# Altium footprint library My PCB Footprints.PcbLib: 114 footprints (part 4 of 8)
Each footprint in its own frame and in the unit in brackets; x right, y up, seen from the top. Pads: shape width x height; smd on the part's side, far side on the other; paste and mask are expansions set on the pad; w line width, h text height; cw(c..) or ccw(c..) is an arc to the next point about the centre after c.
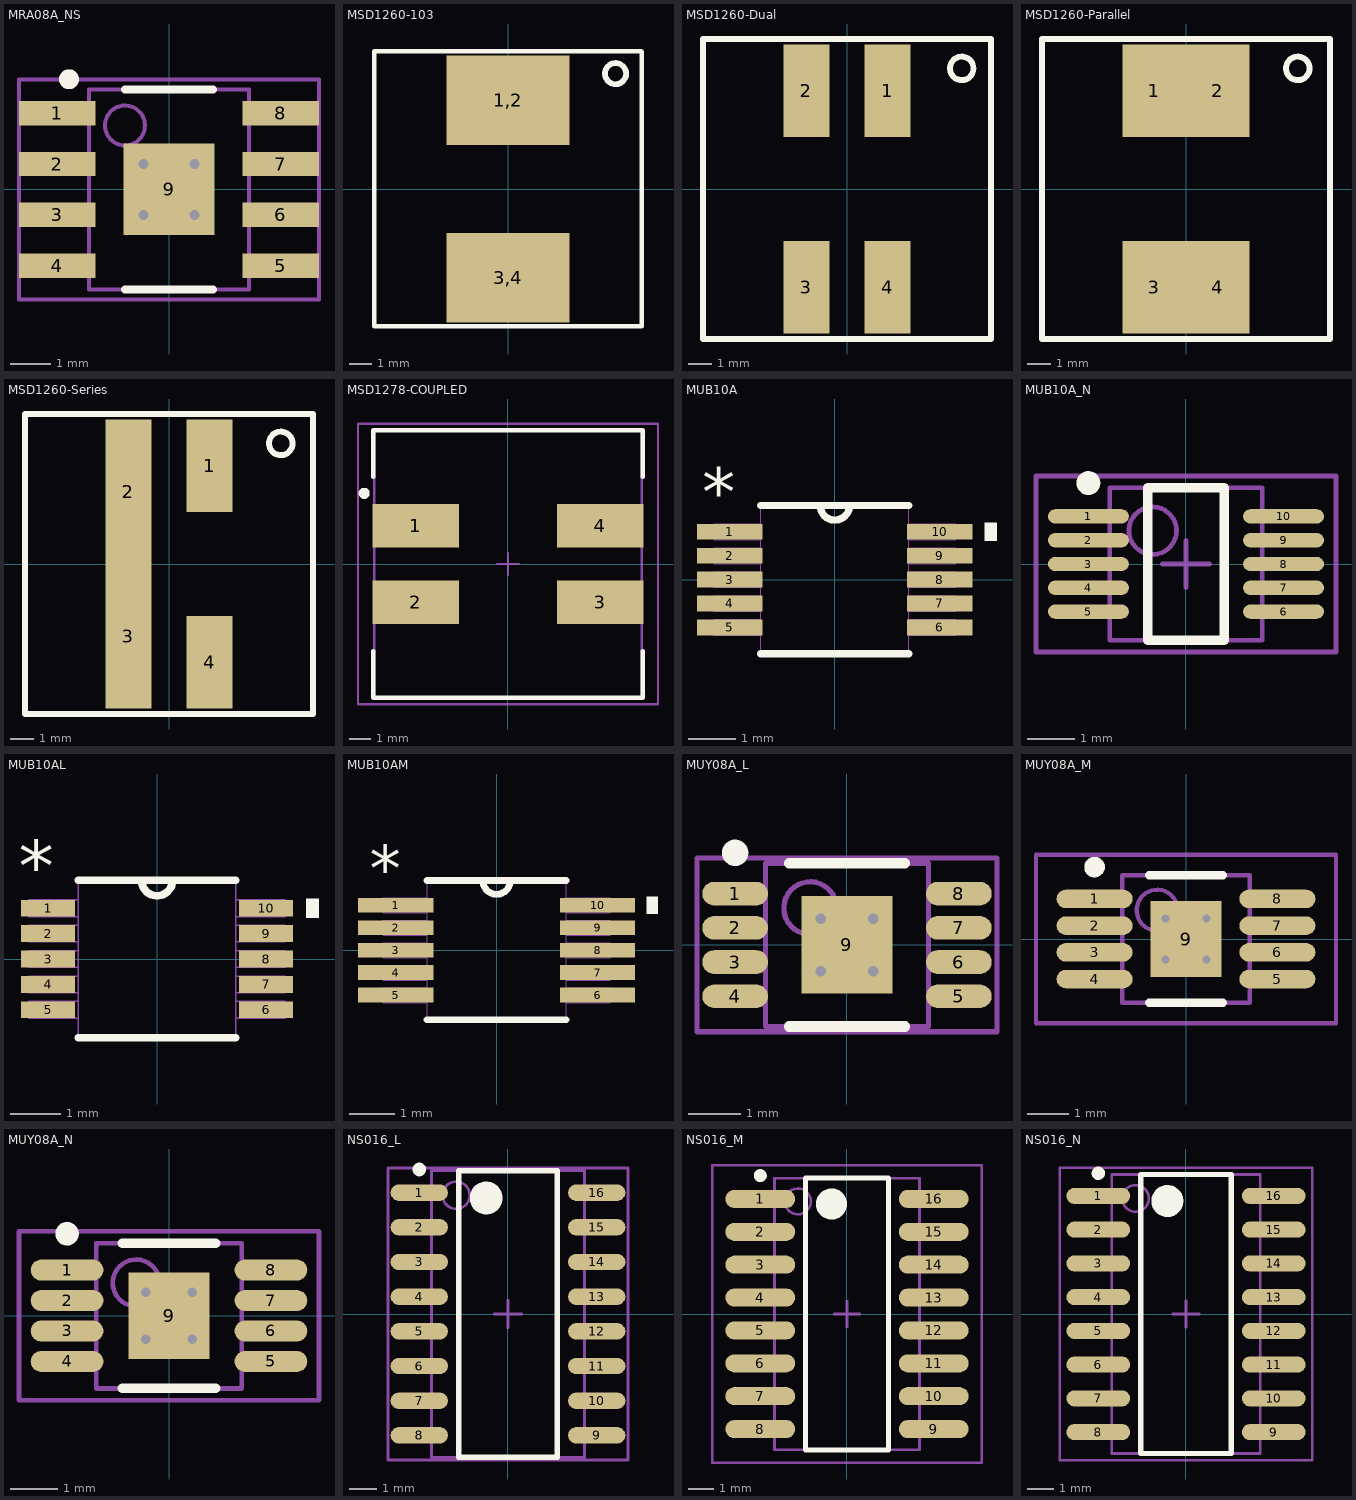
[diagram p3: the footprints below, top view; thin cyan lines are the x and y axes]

## MRA08A_NS [mil] "SOIC, 8-Leads, Body 193x154mil, Pitch 50mil, Exposed Pad, NS Recommended Footprint"
height 66
pads (9):
  rect 75x24 smd: 1(-110,75) 2(-110,25) 3(-110,-25) 4(-110,-75) 5(110,-75) 6(110,-25) 7(110,25) 8(110,75)
  rect 90x90 smd: 9(0,0)
via -25,-25 diameter 25 hole 10
via 25,-25 diameter 25 hole 10
via 25,25 diameter 25 hole 10
via -25,25 diameter 25 hole 10
Top Overlay:
  circle w9.84: c-98.43,108.46 r4.92
  lines w7.87: -43.31,-98.43 43.31,-98.43 ; -43.31,98.43 43.31,98.43
Mechanical 5:
  text ".Designator" at -60,-20 h40
Mechanical 13:
  circle w3.94: c-43.31,62.99 r19.68
  lines w3.94: -78.74,-98.43 78.74,-98.43 78.74,98.43 -78.74,98.43 -78.74,-98.43
Mechanical 15:
  lines w3.94: -19.68,0 19.68,0 ; 0,-19.68 0,19.68 ; -147.64,-108.27 147.64,-108.27 147.64,108.27 -147.64,108.27 -147.64,-108.27
3D body: height 66.14, standoff 0.98, extent -78.74,-98.43 78.74,98.43

## MSD1260-103 [mm]
pads (2):
  rect 5.5x4 smd: 1,2(0,3.978) 3,4(0,-3.978)
Top Overlay:
  circle w0.254: c4.825,5.175 r0.475
  lines w0.2: 6,-6.15 -6,-6.15 -6,6.175 5.975,6.175 6,6.15 6,-6.1

## MSD1260-Dual [mm]
height 6
pads (4):
  rect 2x4 smd: 1(1.75,4.25) 2(-1.75,4.25) 3(-1.75,-4.25) 4(1.75,-4.25)
Top Overlay:
  circle w0.254: c4.953,5.207 r0.508
  lines w0.254: -6.223,-6.477 -6.223,6.477 6.223,6.477 6.223,-6.477 -6.223,-6.477

## MSD1260-Parallel [mm]
height 6
pads (4):
  rect 2.75x4 smd: 1(-1.375,4.25) 2(1.375,4.25) 3(-1.375,-4.25) 4(1.375,-4.25)
Top Overlay:
  circle w0.254: c4.826,5.207 r0.508
  lines w0.254: -6.223,-6.477 6.223,-6.477 6.223,6.477 -6.223,6.477 -6.223,-6.477

## MSD1260-Series [mm]
height 6
pads (4):
  rect 2x4 smd: 1(1.75,4.25) 4(1.75,-4.25)
  rect 2x6.25 smd: 2(-1.75,3.125) 3(-1.75,-3.125)
Top Overlay:
  circle w0.254: c4.826,5.207 r0.508
  lines w0.254: -6.223,-6.477 6.223,-6.477 6.223,6.477 -6.223,6.477 -6.223,-6.477

## MSD1278-COUPLED [mil]
height 316.93
pads (4):
  rect 157x79 smd mask+2: 1(-167.32,69) 2(-167.32,-69) 3(167.32,-69) 4(167.32,69)
Top Overlay:
  circle w10: c-260.41,128.06 r5.03
  lines w7.87: -244.09,-157.48 -244.09,-242.13 244.09,-242.13 244.09,-157.48 ; -244.09,157.48 -244.09,242.13 244.09,242.13 244.09,157.48
Mechanical 5:
  text ".Designator" at -60,-20 h40
Mechanical 13:
  lines w3.94: -242.13,-242.13 -242.13,242.13 242.13,242.13 242.13,-242.13 -242.13,-242.13
Mechanical 15:
  lines w3.94: -19.68,0 19.69,0 ; 0,-19.68 0,19.69 ; -271.65,-253.94 -271.65,253.94 271.65,253.94 271.65,-253.94 -271.65,-253.94
3D body: height 316.93, standoff 0, extent -242.13,-242.13 242.13,242.13

## MUB10A [mil]
pads (10):
  rect 54x13 smd: 1(-86.5,39.37) 2(-86.5,19.68) 3(-86.5,0) 4(-86.5,-19.68) 5(-86.5,-39.37) 6(86.5,-39.37) 7(86.5,-19.68) 8(86.5,0) 9(86.5,19.68) 10(86.5,39.37)
Top Overlay:
  region: 133.5,46.87 133.5,31.87 123.5,31.87 123.5,46.87
  lines w6: -61,-61 61,-61 ; -61,61 61,61 ; -12,61 ccw(c0,61) 12,61
  text "*" at -109.02,52.02 h40
Mechanical 1:
  lines w1: -12,61 ccw(c0,61) 12,61 ; -99.5,-45.87 -99.5,-32.87 -61,-32.87 -61,-45.87 -99.5,-45.87 ; -99.5,-26.18 -99.5,-13.19 -61,-13.19 -61,-26.18 -99.5,-26.18 ; -99.5,-6.5 -99.5,6.5 -61,6.5 -61,-6.5 -99.5,-6.5 ; -99.5,13.19 -99.5,26.18 -61,26.18 -61,13.19 -99.5,13.19 ; -99.5,32.87 -99.5,45.87 -61,45.87 -61,32.87 -99.5,32.87 ; -61,-61 61,-61 61,61 -61,61 -61,-61 ; 61,-45.87 61,-32.87 99.5,-32.87 99.5,-45.87 61,-45.87 ; 61,-26.18 61,-13.19 99.5,-13.19 99.5,-26.18 61,-26.18 ; 61,-6.5 61,6.5 99.5,6.5 99.5,-6.5 61,-6.5 ; 61,13.19 61,26.18 99.5,26.18 99.5,13.19 61,13.19 ; 61,32.87 61,45.87 99.5,45.87 99.5,32.87 61,32.87
  text "*" at -109.02,52.02 h40

## MUB10A_N [mm] "TSSOP, 10-Leads, Body 3x3mm, Pitch 0.5mm, IPC Medium Density"
height 1.09
pads (10):
  oval 1.7x0.3 smd: 1(-2.05,1) 2(-2.05,0.5) 3(-2.05,0) 4(-2.05,-0.5) 5(-2.05,-1) 6(2.05,-1) 7(2.05,-0.5) 8(2.05,0) 9(2.05,0.5) 10(2.05,1)
Top Overlay:
  circle w0.25: c-2.05,1.7 r0.125
  lines w0.2: -0.8,-1.6 -0.8,1.6 0.8,1.6 0.8,-1.6 -0.8,-1.6
Mechanical 5:
  circle w0.1: c-0.7,0.7 r0.5
  lines w0.1: -1.6,-1.6 -1.6,1.6 1.6,1.6 1.6,-1.6 -1.6,-1.6
  text ".Designator" at -1.524,-0.508 h1.02
Mechanical 15:
  lines w0.1: -0.5,0 0.5,0 ; 0,-0.5 0,0.5 ; -3.15,-1.85 -3.15,1.85 3.15,1.85 3.15,-1.85 -3.15,-1.85
3D body: height 1.09, standoff 0, extent -1.6,-1.6 1.6,1.6

## MUB10AL [mil]
pads (10):
  rect 42x13 smd: 1(-84.5,39.37) 2(-84.5,19.68) 3(-84.5,0) 4(-84.5,-19.68) 5(-84.5,-39.37) 6(84.5,-39.37) 7(84.5,-19.68) 8(84.5,0) 9(84.5,19.68) 10(84.5,39.37)
Top Overlay:
  region: 125.5,46.87 125.5,31.87 115.5,31.87 115.5,46.87
  lines w6: -61,-61 61,-61 ; -61,61 61,61 ; -12,61 ccw(c0,61) 12,61
  text "*" at -107.02,52.02 h40
Mechanical 1:
  lines w1: -12,61 ccw(c0,61) 12,61 ; -99.5,-45.87 -99.5,-32.87 -61,-32.87 -61,-45.87 -99.5,-45.87 ; -99.5,-26.18 -99.5,-13.19 -61,-13.19 -61,-26.18 -99.5,-26.18 ; -99.5,-6.5 -99.5,6.5 -61,6.5 -61,-6.5 -99.5,-6.5 ; -99.5,13.19 -99.5,26.18 -61,26.18 -61,13.19 -99.5,13.19 ; -99.5,32.87 -99.5,45.87 -61,45.87 -61,32.87 -99.5,32.87 ; -61,-61 61,-61 61,61 -61,61 -61,-61 ; 61,-45.87 61,-32.87 99.5,-32.87 99.5,-45.87 61,-45.87 ; 61,-26.18 61,-13.19 99.5,-13.19 99.5,-26.18 61,-26.18 ; 61,-6.5 61,6.5 99.5,6.5 99.5,-6.5 61,-6.5 ; 61,13.19 61,26.18 99.5,26.18 99.5,13.19 61,13.19 ; 61,32.87 61,45.87 99.5,45.87 99.5,32.87 61,32.87
  text "*" at -107.02,52.02 h40

## MUB10AM [mil]
pads (10):
  rect 66x13 smd: 1(-88.5,39.37) 2(-88.5,19.68) 3(-88.5,0) 4(-88.5,-19.68) 5(-88.5,-39.37) 6(88.5,-39.37) 7(88.5,-19.68) 8(88.5,0) 9(88.5,19.68) 10(88.5,39.37)
Top Overlay:
  region: 141.5,46.87 141.5,31.87 131.5,31.87 131.5,46.87
  lines w6: -61,-61 61,-61 ; -61,61 61,61 ; -12,61 ccw(c0,61) 12,61
  text "*" at -111.02,52.02 h40
Mechanical 1:
  lines w1: -12,61 ccw(c0,61) 12,61 ; -99.5,-45.87 -99.5,-32.87 -61,-32.87 -61,-45.87 -99.5,-45.87 ; -99.5,-26.18 -99.5,-13.19 -61,-13.19 -61,-26.18 -99.5,-26.18 ; -99.5,-6.5 -99.5,6.5 -61,6.5 -61,-6.5 -99.5,-6.5 ; -99.5,13.19 -99.5,26.18 -61,26.18 -61,13.19 -99.5,13.19 ; -99.5,32.87 -99.5,45.87 -61,45.87 -61,32.87 -99.5,32.87 ; -61,-61 61,-61 61,61 -61,61 -61,-61 ; 61,-45.87 61,-32.87 99.5,-32.87 99.5,-45.87 61,-45.87 ; 61,-26.18 61,-13.19 99.5,-13.19 99.5,-26.18 61,-26.18 ; 61,-6.5 61,6.5 99.5,6.5 99.5,-6.5 61,-6.5 ; 61,13.19 61,26.18 99.5,26.18 99.5,13.19 61,13.19 ; 61,32.87 61,45.87 99.5,45.87 99.5,32.87 61,32.87
  text "*" at -111.02,52.02 h40

## MUY08A_L [mm] "TSOP, 8-Leads, Body 3x3mm, Pitch 0.65mm, Exposed Pad, IPC High Density"
height 1.09
pads (9):
  oval 1.25x0.45 smd: 1(-2.125,0.975) 2(-2.125,0.325) 3(-2.125,-0.325) 4(-2.125,-0.975) 5(2.125,-0.975) 6(2.125,-0.325) 7(2.125,0.325) 8(2.125,0.975)
  rect 1.73x1.85 smd: 9(0,0)
via 0.5,-0.5 diameter 0.4 hole 0.2
via -0.5,-0.5 diameter 0.4 hole 0.2
via 0.5,0.5 diameter 0.4 hole 0.2
via -0.5,0.5 diameter 0.4 hole 0.2
Top Overlay:
  circle w0.25: c-2.125,1.75 r0.125
  lines w0.2: -1.1,-1.55 1.1,-1.55 ; -1.1,1.55 1.1,1.55
Mechanical 5:
  text ".Designator" at -1.524,-0.508 h1.02
Mechanical 13:
  circle w0.1: c-0.7,0.7 r0.5
  lines w0.1: -1.55,-1.55 1.55,-1.55 1.55,1.55 -1.55,1.55 -1.55,-1.55
Mechanical 15:
  lines w0.1: -0.5,0 0.5,0 ; 0,-0.5 0,0.5 ; -2.85,-1.65 2.85,-1.65 2.85,1.65 -2.85,1.65 -2.85,-1.65
3D body: height 1.09, standoff 0, extent -1.549,-1.549 1.549,1.549

## MUY08A_M [mm] "TSOP, 8-Leads, Body 3x3mm, Pitch 0.65mm, Exposed Pad, IPC Low Density"
height 1.09
pads (9):
  oval 1.85x0.45 smd: 1(-2.225,0.975) 2(-2.225,0.325) 3(-2.225,-0.325) 4(-2.225,-0.975) 5(2.225,-0.975) 6(2.225,-0.325) 7(2.225,0.325) 8(2.225,0.975)
  rect 1.73x1.85 smd: 9(0,0)
via 0.5,-0.5 diameter 0.4 hole 0.2
via -0.5,-0.5 diameter 0.4 hole 0.2
via 0.5,0.5 diameter 0.4 hole 0.2
via -0.5,0.5 diameter 0.4 hole 0.2
Top Overlay:
  circle w0.25: c-2.225,1.75 r0.125
  lines w0.2: -0.9,-1.55 0.9,-1.55 ; -0.9,1.55 0.9,1.55
Mechanical 5:
  text ".Designator" at -1.524,-0.508 h1.02
Mechanical 13:
  circle w0.1: c-0.7,0.7 r0.5
  lines w0.1: -1.55,-1.55 1.55,-1.55 1.55,1.55 -1.55,1.55 -1.55,-1.55
Mechanical 15:
  lines w0.1: -0.5,0 0.5,0 ; 0,-0.5 0,0.5 ; -3.65,-2.05 3.65,-2.05 3.65,2.05 -3.65,2.05 -3.65,-2.05
3D body: height 1.09, standoff 0, extent -1.549,-1.549 1.549,1.549

## MUY08A_N [mm] "TSOP, 8-Leads, Body 3x3mm, Pitch 0.65mm, Exposed Pad, IPC Medium Density"
height 1.09
pads (9):
  oval 1.55x0.45 smd: 1(-2.175,0.975) 2(-2.175,0.325) 3(-2.175,-0.325) 4(-2.175,-0.975) 5(2.175,-0.975) 6(2.175,-0.325) 7(2.175,0.325) 8(2.175,0.975)
  rect 1.73x1.85 smd: 9(0,0)
via 0.5,-0.5 diameter 0.4 hole 0.2
via -0.5,-0.5 diameter 0.4 hole 0.2
via 0.5,0.5 diameter 0.4 hole 0.2
via -0.5,0.5 diameter 0.4 hole 0.2
Top Overlay:
  circle w0.25: c-2.175,1.75 r0.125
  lines w0.2: -1,-1.55 1,-1.55 ; -1,1.55 1,1.55
Mechanical 5:
  text ".Designator" at -1.524,-0.508 h1.02
Mechanical 13:
  circle w0.1: c-0.7,0.7 r0.5
  lines w0.1: -1.55,-1.55 1.55,-1.55 1.55,1.55 -1.55,1.55 -1.55,-1.55
Mechanical 15:
  lines w0.1: -0.5,0 0.5,0 ; 0,-0.5 0,0.5 ; -3.2,-1.8 3.2,-1.8 3.2,1.8 -3.2,1.8 -3.2,-1.8
3D body: height 1.09, standoff 0, extent -1.549,-1.549 1.549,1.549

## NS016_L [mm] "16-Pin Small Outline Package 1.27 mm Pitch, IPC High Density"
height 2
pads (16):
  oval 2.1x0.6 smd: 1(-3.25,4.445) 2(-3.25,3.175) 3(-3.25,1.905) 4(-3.25,0.635) 5(-3.25,-0.635) 6(-3.25,-1.905) 7(-3.25,-3.175) 8(-3.25,-4.445) 9(3.25,-4.445) 10(3.25,-3.175) 11(3.25,-1.905) 12(3.25,-0.635) 13(3.25,0.635) 14(3.25,1.905) 15(3.25,3.175) 16(3.25,4.445)
Top Overlay:
  circle w0.25: c-3.25,5.295 r0.125
  circle w0.6: c-0.8,4.25 r0.3
  lines w0.2: -1.8,-5.25 -1.8,5.25 1.8,5.25 1.8,-5.25 -1.8,-5.25
Mechanical 5:
  text ".Designator" at -0.508,4.826 h1.02
Mechanical 13:
  circle w0.1: c-1.9,4.35 r0.5
  lines w0.1: -2.8,-5.25 -2.8,5.25 2.8,5.25 2.8,-5.25 -2.8,-5.25
Mechanical 15:
  lines w0.1: -0.5,0 0.5,0 ; 0,-0.5 0,0.5 ; -4.4,-5.35 -4.4,5.35 4.4,5.35 4.4,-5.35 -4.4,-5.35
3D body: height 2, standoff 0, extent -2.8,-5.25 2.8,5.25

## NS016_M [mm] "16-Pin Small Outline Package 1.27 mm Pitch, IPC Low Density"
height 2
pads (16):
  oval 2.7x0.7 smd: 1(-3.35,4.445) 2(-3.35,3.175) 3(-3.35,1.905) 4(-3.35,0.635) 5(-3.35,-0.635) 6(-3.35,-1.905) 7(-3.35,-3.175) 8(-3.35,-4.445) 9(3.35,-4.445) 10(3.35,-3.175) 11(3.35,-1.905) 12(3.35,-0.635) 13(3.35,0.635) 14(3.35,1.905) 15(3.35,3.175) 16(3.35,4.445)
Top Overlay:
  circle w0.25: c-3.35,5.345 r0.125
  circle w0.6: c-0.6,4.25 r0.3
  lines w0.2: -1.6,-5.25 -1.6,5.25 1.6,5.25 1.6,-5.25 -1.6,-5.25
Mechanical 5:
  text ".Designator" at -0.508,4.826 h1.02
Mechanical 13:
  circle w0.1: c-1.9,4.35 r0.5
  lines w0.1: -2.8,-5.25 -2.8,5.25 2.8,5.25 2.8,-5.25 -2.8,-5.25
Mechanical 15:
  lines w0.1: -0.5,0 0.5,0 ; 0,-0.5 0,0.5 ; -5.2,-5.75 -5.2,5.75 5.2,5.75 5.2,-5.75 -5.2,-5.75
3D body: height 2, standoff 0, extent -2.8,-5.25 2.8,5.25

## NS016_N [mm] "16-Pin Small Outline Package 1.27 mm Pitch, IPC Medium Density"
height 2
pads (16):
  oval 2.4x0.6 smd: 1(-3.3,4.445) 2(-3.3,3.175) 3(-3.3,1.905) 4(-3.3,0.635) 5(-3.3,-0.635) 6(-3.3,-1.905) 7(-3.3,-3.175) 8(-3.3,-4.445) 9(3.3,-4.445) 10(3.3,-3.175) 11(3.3,-1.905) 12(3.3,-0.635) 13(3.3,0.635) 14(3.3,1.905) 15(3.3,3.175) 16(3.3,4.445)
Top Overlay:
  circle w0.25: c-3.3,5.295 r0.125
  circle w0.6: c-0.7,4.25 r0.3
  lines w0.2: -1.7,-5.25 -1.7,5.25 1.7,5.25 1.7,-5.25 -1.7,-5.25
Mechanical 5:
  text ".Designator" at -0.508,4.826 h1.02
Mechanical 13:
  circle w0.1: c-1.9,4.35 r0.5
  lines w0.1: -2.8,-5.25 -2.8,5.25 2.8,5.25 2.8,-5.25 -2.8,-5.25
Mechanical 15:
  lines w0.1: -0.5,0 0.5,0 ; 0,-0.5 0,0.5 ; -4.75,-5.5 -4.75,5.5 4.75,5.5 4.75,-5.5 -4.75,-5.5
3D body: height 2, standoff 0, extent -2.8,-5.25 2.8,5.25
